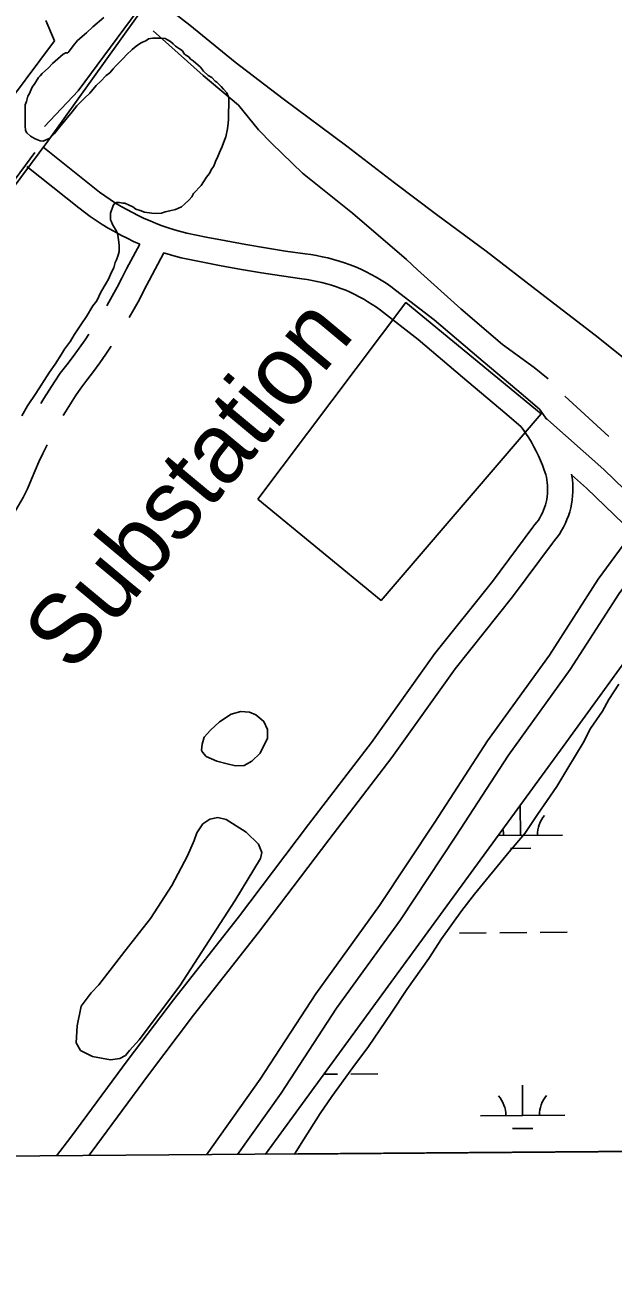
# Model space of a CAD drawing. Extents: x 3540316 to 3578335, y 553172 to 578787.
# Drawn here: x 3562239 to 3562936, y 558573 to 560053 of the extents above; entities that cross this region are included whole.
import ezdxf

# ---------------------------------------------------------------- set-up
doc = ezdxf.new("R2010")
doc.units = 0
for name, color, linetype in [('V-GRID-FRAM', 7, 'Continuous'), ('V-RAIL-TRAK', 7, 'Continuous'), ('V-ROAD-CNTR', 7, 'Continuous'), ('V-SITE-OTLN', 7, 'Continuous'), ('V-SITE-OTLN-IDEN', 7, 'Continuous'), ('V-SITE-VEGE', 7, 'Continuous'), ('V-TOPO-SHOR', 7, 'Continuous'), ('V-WETL-SWMP', 7, 'Continuous')]:
    doc.layers.add(name, color=color, linetype=linetype)

msp = doc.modelspace()

# ---------------------------------------------------------------- linework, layer by layer
at = {"layer": 'V-GRID-FRAM'}
msp.add_lwpolyline([(3544387.2, 576756), (3576013, 576999.8), (3576161.1, 558817.2), (3544519.4, 558573.3), (3544387.2, 576756)], dxfattribs=at)
at = {"layer": 'V-RAIL-TRAK'}
msp.add_lwpolyline([(3562390.8, 560087.2), (3562434.4, 560053), (3562488, 560009.1), (3562545.1, 559965.4), (3562620.5, 559909.4), (3562676.9, 559865.7), (3562726.9, 559828.3), (3562786, 559784.6), (3562850.4, 559734.8), (3562915.2, 559684.9), (3562970, 559641)], dxfattribs=at)
at = {"layer": 'V-ROAD-CNTR'}
for points in [[(3562261.8, 559932.7), (3562301.8, 559974.9), (3563224.6, 561223.2), (3563256.3, 561282.2)], [(3563261.4, 561261.5), (3563251.4, 561219.6), (3562613.7, 560401.7), (3562266, 559915.3), (3561372.7, 558712.3), (3561361.3, 558699.6)], [(3562259.8, 559908.7), (3562321.1, 559859.6), (3562327.2, 559854.9), (3562333.4, 559850.4), (3562339.8, 559846), (3562346.2, 559841.8), (3562352.8, 559837.8), (3562359.5, 559834), (3562366.2, 559830.4), (3562373.1, 559826.9), (3562380.1, 559823.6), (3562387.1, 559820.5), (3562394.2, 559817.6), (3562401.4, 559814.9), (3562408.7, 559812.4), (3562416, 559810.1), (3562423.4, 559808), (3562430.7, 559806.1), (3562453.7, 559801.4), (3562477.2, 559796.8), (3562500.6, 559792.6), (3562524.1, 559788.6), (3562547.7, 559784.8), (3562571.2, 559781.4), (3562577.7, 559780.5), (3562584.5, 559779.4), (3562591.3, 559778.1), (3562598, 559776.6), (3562604.7, 559774.9), (3562611.3, 559772.9), (3562617.8, 559770.8), (3562624.3, 559768.4), (3562630.7, 559765.9), (3562637.1, 559763.1), (3562643.3, 559760.2), (3562649.4, 559757), (3562655.5, 559753.7), (3562661.4, 559750.2), (3562667.2, 559746.5), (3562672.9, 559742.6), (3562678.4, 559738.5), (3562724.2, 559703.1), (3562777.3, 559657.9), (3562827.5, 559615.5), (3562849, 559597.1), (3562854, 559590.3), (3562857.7, 559584.9)], [(3562250.4, 559901.7), (3561374.3, 558712.5)], [(3562241, 559885.3), (3562302.6, 559836), (3562309.3, 559830.9), (3562316.1, 559825.9), (3562323.1, 559821.1), (3562330.3, 559816.4), (3562337.5, 559812), (3562344.9, 559807.8), (3562352.4, 559803.8), (3562359.9, 559799.9), (3562367.6, 559796.3), (3562374.9, 559793.1)], [(3562375.1, 559793), (3562359.3, 559763.6), (3562353.7, 559752.4), (3562348, 559741.7), (3562342.1, 559731), (3562336.1, 559720.4), (3562335.7, 559719.9)], [(3562403, 559782.7), (3562407.3, 559781.4), (3562415.5, 559779), (3562423.9, 559776.9), (3562447.9, 559771.9), (3562471.6, 559767.3), (3562495.4, 559763), (3562519.3, 559759), (3562543.1, 559755.2), (3562567.1, 559751.6), (3562573.4, 559750.8), (3562579.3, 559749.9), (3562585.1, 559748.8), (3562590.9, 559747.4), (3562596.7, 559746), (3562602.4, 559744.3), (3562608.1, 559742.4), (3562613.6, 559740.4), (3562619.2, 559738.2), (3562624.6, 559735.8), (3562630, 559733.3), (3562635.3, 559730.5), (3562640.5, 559727.7), (3562645.6, 559724.6), (3562650.7, 559721.4), (3562655.6, 559718.1), (3562660.4, 559714.5), (3562705.3, 559679.8), (3562757.9, 559635), (3562808.1, 559592.7), (3562826.9, 559576.5), (3562829.6, 559572.8), (3562833, 559567.9), (3562836.3, 559562.8), (3562839.4, 559557.6), (3562842.4, 559552.3), (3562845.2, 559546.9), (3562847.8, 559541.5), (3562850.3, 559535.9), (3562852.5, 559530.3), (3562854.6, 559524.6), (3562856.4, 559519.2), (3562857.2, 559516.2), (3562857.8, 559513), (3562858.3, 559509.7), (3562858.6, 559506.4), (3562858.7, 559503), (3562858.7, 559499.7), (3562858.5, 559496.4), (3562858.1, 559493.1), (3562857.6, 559489.8), (3562856.9, 559486.5), (3562856.1, 559483.3), (3562855, 559480.2), (3562853.9, 559477), (3562852.5, 559474), (3562851.1, 559471), (3562849.4, 559468.1), (3562847.7, 559465.3), (3562845.8, 559462.6), (3562843.7, 559459.9), (3562841, 559456.7), (3562793.4, 559392.3), (3562725, 559306.6), (3562649.7, 559201.1), (3562575.2, 559103.5), (3562491.9, 558993.7), (3562414.9, 558895.5), (3562361, 558824.5), (3562293.2, 558732.2), (3562276.1, 558710.2)], [(3562403.5, 559782.6), (3562385.9, 559749.7), (3562380.3, 559738.7), (3562374.4, 559727.4), (3562368.3, 559716.3), (3562362.2, 559705.7)], [(3562314.5, 559686), (3562310, 559679.3), (3562303, 559669.3), (3562295.8, 559659.4), (3562288.5, 559649.7), (3562280.6, 559639.6), (3562273.7, 559629.4), (3562267.3, 559619.5), (3562261.1, 559609.5), (3562257.7, 559603.7)], [(3562341, 559671.7), (3562334.7, 559662.3), (3562327.4, 559651.9), (3562319.9, 559641.6), (3562312.3, 559631.4), (3562304.9, 559621.9), (3562298.8, 559612.9), (3562292.7, 559603.5), (3562286.8, 559593.9), (3562284.2, 559589.5)], [(3562855.5, 559587.4), (3562925.2, 559525.3), (3562999.3, 559453.7), (3562943.5, 559378.1), (3562885.6, 559287.9), (3562812.2, 559186.1), (3562749.9, 559089.8), (3562684, 558990.4), (3562608.4, 558885.4), (3562542.7, 558784.5), (3562490.9, 558711.8)], [(3562264.9, 559554.5), (3562260, 559544.5), (3562255.3, 559534.4), (3562250.7, 559524.1), (3562246.3, 559513.7), (3562241.8, 559502.5), (3562236.4, 559492.2), (3562231.1, 559482.6), (3562225.6, 559473.1), (3562220.7, 559465)], [(3562887, 559519.7), (3562887.4, 559517.9), (3562888.1, 559513.2), (3562888.5, 559508.4), (3562888.7, 559503.5), (3562888.7, 559498.7), (3562888.4, 559493.9), (3562887.9, 559489.1), (3562887.1, 559484.3), (3562886.1, 559479.6), (3562884.9, 559474.9), (3562883.4, 559470.3), (3562881.7, 559465.8), (3562879.8, 559461.4), (3562877.6, 559457), (3562875.3, 559452.8), (3562872.7, 559448.7), (3562869.9, 559444.8), (3562867, 559440.9), (3562864.4, 559438), (3562817.2, 559374.1), (3562749, 559288.5), (3562673.9, 559183.3), (3562599.1, 559085.3), (3562515.6, 558975.4), (3562438.7, 558877.2), (3562385.1, 558806.5), (3562317.1, 558714.1), (3562314.3, 558710.5)], [(3562887.2, 559519), (3562904.8, 559503.3), (3562959.6, 559450.4), (3562918.8, 559395.1), (3562860.8, 559304.8), (3562787.4, 559203), (3562724.8, 559106.3), (3562659.3, 559007.4), (3562583.6, 558902.4), (3562517.9, 558801.4), (3562453.9, 558711.5)]]:
    msp.add_lwpolyline(points, dxfattribs=at)
at = {"layer": 'V-SITE-OTLN'}
msp.add_lwpolyline([(3562514.9, 559490.1), (3562690.7, 559723.6), (3562850.9, 559591.5), (3562661.2, 559369.9)], close=True, dxfattribs=at)
at = {"layer": 'V-SITE-VEGE'}
for p, q in [((3562332.1, 560062.1), (3562319.2, 560051.1)), ((3562311.6, 560044), (3562300.9, 560034.8)), ((3562319.2, 560051.1), (3562311.6, 560044)), ((3562296, 560028.6), (3562291.5, 560022.4)), ((3562300.9, 560034.8), (3562296, 560028.6)), ((3562366, 560024.1), (3562370.5, 560028)), ((3562370.5, 560028), (3562375.8, 560031.6)), ((3562375.8, 560031.6), (3562378.1, 560032.9)), ((3562378.1, 560032.9), (3562382.1, 560034.6)), ((3562382.1, 560034.6), (3562385.2, 560036.8)), ((3562385.2, 560036.8), (3562390.1, 560037.7)), ((3562390.1, 560037.7), (3562399, 560037.6)), ((3562399, 560037.6), (3562405.2, 560037.1)), ((3562405.2, 560037.1), (3562407.8, 560035.8)), ((3562407.8, 560035.8), (3562411.4, 560033.5)), ((3562411.4, 560033.5), (3562414.4, 560030.8)), ((3562414.4, 560030.8), (3562417.1, 560028.1)), ((3562417.1, 560028.1), (3562421.9, 560025)), ((3562421.9, 560025), (3562425, 560022.8)), ((3562283.9, 560018.5), (3562271.4, 560007.5)), ((3562287, 560020.2), (3562283.9, 560018.5)), ((3562289.7, 560020.2), (3562287, 560020.2)), ((3562291.5, 560022.4), (3562289.7, 560020.2)), ((3562346.8, 560005.2), (3562355.3, 560013.5)), ((3562355.3, 560013.5), (3562359.3, 560017.9)), ((3562359.3, 560017.9), (3562366, 560024.1)), ((3562425, 560022.8), (3562428.1, 560018.7)), ((3562428.1, 560018.7), (3562430.3, 560017)), ((3562430.3, 560017), (3562433.4, 560015.2)), ((3562433.4, 560015.2), (3562434.7, 560012.9)), ((3562434.7, 560012.9), (3562438.3, 560010.7)), ((3562438.3, 560010.7), (3562447.1, 560003.1)), ((3562259.3, 559995.6), (3562256.6, 559993)), ((3562266.5, 560002.2), (3562259.3, 559995.6)), ((3562271.4, 560007.5), (3562266.5, 560002.2)), ((3562335.2, 559993.3), (3562339.2, 559996.3)), ((3562339.2, 559996.3), (3562343.2, 560001.2)), ((3562343.2, 560001.2), (3562346.8, 560005.2)), ((3562447.1, 560003.1), (3562450.6, 559998.6)), ((3562450.6, 559998.6), (3562455.9, 559993.2)), ((3562250.4, 559983.7), (3562247.2, 559979.3)), ((3562254.8, 559990.8), (3562250.4, 559983.7)), ((3562256.6, 559993), (3562254.8, 559990.8)), ((3562315.5, 559972.1), (3562323.1, 559981.4)), ((3562323.1, 559981.4), (3562328.5, 559986.2)), ((3562328.5, 559986.2), (3562335.2, 559993.3)), ((3562455.9, 559993.2), (3562460.3, 559991)), ((3562460.3, 559991), (3562464.3, 559986.5)), ((3562464.3, 559986.5), (3562466.5, 559985.2)), ((3562466.5, 559985.2), (3562471.3, 559980.3)), ((3562471.3, 559980.3), (3562474.4, 559977.1)), ((3562242.3, 559968.7), (3562240.4, 559962.5)), ((3562243.6, 559971.3), (3562242.3, 559968.7)), ((3562247.2, 559979.3), (3562243.6, 559971.3)), ((3562300.3, 559957.1), (3562309.2, 559966.4)), ((3562309.2, 559966.4), (3562315.5, 559972.1)), ((3562474.4, 559977.1), (3562478.3, 559972.7)), ((3562478.3, 559972.7), (3562480.5, 559966.9)), ((3562480.5, 559966.9), (3562480.3, 559941.1)), ((3562239.1, 559958.5), (3562238.9, 559933.6)), ((3562240.4, 559962.5), (3562239.1, 559958.5)), ((3562294.9, 559950.1), (3562300.3, 559957.1)), ((3562279.7, 559932), (3562294.9, 559950.1)), ((3562479.9, 559936.7), (3562478.9, 559930.1)), ((3562480.3, 559941.1), (3562479.9, 559936.7)), ((3562238.9, 559933.6), (3562239.3, 559927.9)), ((3562239.3, 559927.9), (3562241, 559925.2)), ((3562241, 559925.2), (3562245.4, 559921.2)), ((3562245.4, 559921.2), (3562250.8, 559918)), ((3562268.1, 559918.8), (3562273.9, 559924.5)), ((3562273.9, 559924.5), (3562279.7, 559932)), ((3562478.9, 559930.1), (3562477.1, 559920.3)), ((3562250.8, 559918), (3562256.9, 559915.8)), ((3562256.9, 559915.8), (3562260.5, 559915.3)), ((3562260.5, 559915.3), (3562268.1, 559918.8)), ((3562472.5, 559908.8), (3562470.7, 559904.4)), ((3562475.3, 559916.3), (3562472.5, 559908.8)), ((3562477.1, 559920.3), (3562475.3, 559916.3)), ((3562467.6, 559896.9), (3562464.9, 559891.1)), ((3562470.7, 559904.4), (3562467.6, 559896.9)), ((3562457.2, 559876.5), (3562454.1, 559872.6)), ((3562460.4, 559882.3), (3562457.2, 559876.5)), ((3562462.6, 559885.4), (3562460.4, 559882.3)), ((3562464.9, 559891.1), (3562462.6, 559885.4)), ((3562447.8, 559862.8), (3562438.8, 559853.2)), ((3562450.5, 559866.8), (3562447.8, 559862.8)), ((3562454.1, 559872.6), (3562450.5, 559866.8)), ((3562436.6, 559849.2), (3562433.5, 559845.6)), ((3562438.8, 559853.2), (3562436.6, 559849.2)), ((3562342.9, 559837.5), (3562340.2, 559829.9)), ((3562344.2, 559840.6), (3562342.9, 559837.5)), ((3562347.4, 559842.3), (3562344.2, 559840.6)), ((3562350.9, 559842.3), (3562347.4, 559842.3)), ((3562354.9, 559841.8), (3562350.9, 559842.3)), ((3562357.1, 559841.8), (3562354.9, 559841.8)), ((3562362.4, 559839.1), (3562357.1, 559841.8)), ((3562366.8, 559837.3), (3562362.4, 559839.1)), ((3562370.4, 559834.6), (3562366.8, 559837.3)), ((3562375.2, 559832.8), (3562370.4, 559834.6)), ((3562380.6, 559831), (3562375.2, 559832.8)), ((3562410.7, 559832.5), (3562405, 559831.2)), ((3562417.4, 559834.2), (3562410.7, 559832.5)), ((3562424.5, 559837.3), (3562417.4, 559834.2)), ((3562428.1, 559840.4), (3562424.5, 559837.3)), ((3562433.5, 559845.6), (3562428.1, 559840.4)), ((3562340.2, 559829.9), (3562340.1, 559821.9)), ((3562340.1, 559821.9), (3562341.4, 559819.3)), ((3562341.4, 559819.3), (3562342.7, 559816.2)), ((3562389.4, 559829.6), (3562380.6, 559831)), ((3562394.3, 559829.5), (3562389.4, 559829.6)), ((3562400.5, 559829.9), (3562394.3, 559829.5)), ((3562405, 559831.2), (3562400.5, 559829.9)), ((3562342.7, 559816.2), (3562346.2, 559810.4)), ((3562346.2, 559810.4), (3562348.4, 559805.9)), ((3562348.4, 559805.9), (3562349.3, 559801)), ((3562349.3, 559801), (3562350.1, 559795.2)), ((3562350.1, 559795.2), (3562350.5, 559790.8)), ((3562350.5, 559790.8), (3562350.5, 559784.2)), ((3562347.3, 559774.4), (3562345.9, 559771.3)), ((3562349.1, 559779.7), (3562347.3, 559774.4)), ((3562350.5, 559784.2), (3562349.1, 559779.7)), ((3562341.4, 559759.8), (3562337.8, 559751.4)), ((3562344.1, 559764.7), (3562341.4, 559759.8)), ((3562345.9, 559771.3), (3562344.1, 559764.7)), ((3562335.1, 559746.5), (3562328.8, 559735.9)), ((3562337.8, 559751.4), (3562335.1, 559746.5)), ((3562328.8, 559735.9), (3562323.9, 559725.8)), ((3562319.4, 559719.6), (3562311.7, 559707.2)), ((3562323.9, 559725.8), (3562319.4, 559719.6)), ((3562311.7, 559707.2), (3562305.9, 559698.4)), ((3562296.9, 559685.2), (3562292.9, 559677.6)), ((3562305.9, 559698.4), (3562296.9, 559685.2)), ((3562292.9, 559677.6), (3562285.7, 559668.4)), ((3562282.1, 559662.2), (3562274.5, 559650.3)), ((3562285.7, 559668.4), (3562282.1, 559662.2)), ((3562267.8, 559641), (3562251.6, 559615.4)), ((3562274.5, 559650.3), (3562267.8, 559641)), ((3562251.6, 559615.4), (3562241.7, 559600.8)), ((3562241.7, 559600.8), (3562235, 559588.9)), ((3562931.3, 559252.2), (3562943.3, 559270.5)), ((3562923.7, 559238.2), (3562931.3, 559252.2)), ((3562909.6, 559217.8), (3562923.7, 559238.2)), ((3562901, 559200.5), (3562909.6, 559217.8)), ((3562882.5, 559170.4), (3562901, 559200.5)), ((3562869.5, 559148.8), (3562882.5, 559170.4)), ((3562846.7, 559115.5), (3562869.5, 559148.8)), ((3562831.5, 559092.9), (3562846.7, 559115.5)), ((3562813.1, 559071.4), (3562831.5, 559092.9)), ((3562772, 559020.8), (3562813.1, 559071.4)), ((3562756.8, 559001.4), (3562772, 559020.8)), ((3562732.9, 558968), (3562756.8, 559001.4)), ((3562717.7, 558944.4), (3562732.9, 558968)), ((3562691.7, 558907.8), (3562717.7, 558944.4)), ((3562673.3, 558879.8), (3562691.7, 558907.8)), ((3562646.2, 558839.9), (3562673.3, 558879.8)), ((3562627.8, 558815.2), (3562646.2, 558839.9)), ((3562602.8, 558780.8), (3562627.8, 558815.2)), ((3562588.7, 558760.3), (3562602.8, 558780.8)), ((3562569.2, 558729.1), (3562588.7, 558760.3)), ((3562558.5, 558712.3), (3562569.2, 558729.1)), ((3563763.7, 558721.6), (3562558.5, 558712.3))]:
    msp.add_line(p, q, dxfattribs=at)
at = {"layer": 'V-TOPO-SHOR'}
msp.add_line((3562879.1, 559612.5), (3562931.5, 559564.7), dxfattribs=at)
for points in [[(3562390.8, 560046.4), (3562450.3, 559993.2), (3562492, 559958.1), (3562515.7, 559928.6), (3562531.4, 559912.7), (3562568.1, 559877.3), (3562627.2, 559829.9), (3562691.3, 559774.9), (3562704.3, 559762.6), (3562755.8, 559716.2), (3562805.1, 559673.9), (3562842.8, 559646.6), (3562859.4, 559632.9)], [(3562453.7, 559184.6), (3562466.3, 559179.1), (3562478.4, 559175.8), (3562488.3, 559173.5), (3562498.7, 559173.9), (3562507.7, 559178.8), (3562517.7, 559188.6), (3562526.4, 559206.2), (3562526.5, 559216.5), (3562522.1, 559226), (3562512.7, 559233.8), (3562505, 559237), (3562494.7, 559238), (3562483.4, 559234.9), (3562469.3, 559225.5), (3562458.9, 559215.7), (3562451.1, 559207.6), (3562448.8, 559199.1), (3562448.3, 559191.9), (3562449.2, 559189.6), (3562453.7, 559184.6)], [(3562449.9, 559104.4), (3562458.1, 559110.2), (3562467.6, 559111.9), (3562477.5, 559109.6), (3562501.2, 559094.5), (3562515.6, 559080.4), (3562519.6, 559070.5), (3562518.1, 559063.3), (3562487.6, 559013), (3562422.3, 558912), (3562374, 558847.9), (3562362.7, 558835.3), (3562358.1, 558829.5), (3562351.3, 558825.9), (3562340, 558824.2), (3562318.9, 558828), (3562304.5, 558835.3), (3562299.6, 558844.4), (3562300.6, 558864.7), (3562305.3, 558888.1), (3562317.2, 558903.8), (3562326.3, 558913.2), (3562357.2, 558953.1), (3562387.7, 558992.1), (3562412.8, 559031.1), (3562431.6, 559066.6), (3562439.4, 559084.6), (3562442.6, 559093.6), (3562449.9, 559104.4)]]:
    msp.add_lwpolyline(points, dxfattribs=at)
at = {"layer": 'V-WETL-SWMP'}
for p, q in [((3562263.6, 560058.7), (3562273.8, 560034.5)), ((3562273.8, 560034.5), (3561455.9, 558938.3)), ((3562877.2, 559196.2), (3563006, 559374.4)), ((3562524.1, 558712.1), (3562877.2, 559196.2)), ((3562826.5, 559090.8), (3562826.3, 559126.4)), ((3562800.1, 559090.6), (3562876.5, 559091.2)), ((3562814.7, 559075.2), (3562838.7, 559075.4)), ((3562754, 558974.8), (3562786, 558975)), ((3562802, 558975.1), (3562834, 558975.4)), ((3562850, 558975.5), (3562882, 558975.8)), ((3562593.4, 558807), (3562609.4, 558807.2)), ((3562625.4, 558807.3), (3562657.4, 558807.5)), ((3562829.1, 558758.1), (3562828.8, 558794.1)), ((3562779.1, 558757.7), (3562879.1, 558758.5)), ((3562817.2, 558742.6), (3562841.2, 558742.8)), ((3563763.8, 558721.6), (3562524.1, 558712.1))]:
    msp.add_line(p, q, dxfattribs=at)
for centre, start, end in [((3562881.8, 559091.7), 139.6699, 181.2135), ((3562771.3, 559090.8), 359.6699, 12.2031), ((3562773.9, 558758.2), 359.6699, 41.2135), ((3562884.3, 558759), 139.6699, 181.2135)]:
    msp.add_arc(centre, 35.2, start, end, dxfattribs=at)

# ---------------------------------------------------------------- texts
at = {"layer": 'V-SITE-OTLN-IDEN'}
msp.add_text('Substation', height=83, rotation=50.1678, dxfattribs=at).set_placement((3562295, 559282))

doc.saveas('drawing.dxf')
